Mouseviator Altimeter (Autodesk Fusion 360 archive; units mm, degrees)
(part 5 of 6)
sketch "Stepper Ear Pipe Outline" plane through (0, 39, 0) normal (0, 1, 0) x axis (-1, 0, 0)
  line L1 (-36.4994, -34.1766) -> (-41.1157, -22.3885)
  line L2 (-23.2139, -41.1177) -> (-33.6166, -37.0564)
  curve K1 (-21.3665, -41.4655) -> (-21.9088, -41.4365)
  line L3 (28.9018, -41.4655) -> (-21.3665, -41.4655)
  line L4 (41.4655, 20.5361) -> (41.4655, -28.9018)
  curve K2 (41.4365, 21.0784) -> (41.4655, 20.5361)
  line L5 (36.4994, 34.1766) -> (41.1157, 22.3885)
  line L6 (26.5185, 40.8706) -> (34.1546, 36.8093)
  line L7 (-24.1231, 41.4655) -> (24.1331, 41.4655)
  line L8 (-33.6166, 37.0564) -> (-26.5251, 40.8618)
  line L9 (-41.1157, 22.3885) -> (-36.4994, 34.1766)
  line L10 (12.6119, 7.2025) -> (15.0791, 9.6697)
  line L11 (20.0288, 4.7199) -> (17.5616, 2.2528)
  line L12 (-2.2528, -17.5616) -> (-4.7199, -20.0288)
  line L13 (-9.6697, -15.0791) -> (-7.2025, -12.6119)
  line L14 (-41.4655, -20.5361) -> (-41.4655, 20.5361)
  arc A1 centre (-36.3855, -20.5361) radius 5.08 clockwise from (-41.1157, -22.3885) to (-41.4655, -20.5361)
  arc A2 centre (-31.7692, -32.3242) radius 5.08 clockwise from (-33.6166, -37.0564) to (-36.4994, -34.1766)
  arc A3 centre (-21.3665, -36.3855) radius 5.08 clockwise from (-21.9088, -41.4365) to (-23.2139, -41.1177)
  arc A4 centre (28.9018, -28.9018) radius 12.5637 clockwise from (41.4655, -28.9018) to (28.9018, -41.4655)
  arc A5 centre (36.3855, 20.5361) radius 5.08 clockwise from (41.1157, 22.3885) to (41.4365, 21.0784)
  arc A6 centre (31.7692, 32.3242) radius 5.08 clockwise from (34.1546, 36.8093) to (36.4994, 34.1766)
  arc A7 centre (24.1331, 36.3855) radius 5.08 clockwise from (24.1331, 41.4655) to (26.5185, 40.8706)
  arc A8 centre (-24.1231, 36.3855) radius 5.08 clockwise from (-26.5251, 40.8618) to (-24.1231, 41.4655)
  arc A9 centre (-31.7692, 32.3242) radius 5.08 clockwise from (-36.4994, 34.1766) to (-33.6166, 37.0564)
  arc A10 centre (-36.3855, 20.5361) radius 5.08 clockwise from (-41.4655, 20.5361) to (-41.1157, 22.3885)
  circle C1 centre (-18.76, 36.96) radius 1
  circle C2 centre (31.4309, 31.4309) radius 2.159
  circle C3 centre (-31.4309, -31.4309) radius 2.159
  circle C4 centre (-18.76, -36.96) radius 1
  circle C5 centre (18.76, 36.96) radius 1
  circle C6 centre (-31.4309, 31.4309) radius 2.159
  circle C7 centre (0, 0) radius 5
  circle C8 centre (-36.96, 18.76) radius 1
  circle C9 centre (36.96, 18.76) radius 1
  circle C10 centre (-36.96, -18.76) radius 1
  arc A11 centre (5.1796, -5.1796) radius 14.4414 clockwise from (12.6119, 7.2025) to (17.5616, 2.2528)
  arc A12 centre (17.5539, 7.1948) radius 3.5 clockwise from (15.0791, 9.6697) to (20.0288, 4.7199)
  circle C11 centre (17.5539, 7.1948) radius 2
  arc A13 centre (5.1796, -5.1796) radius 14 clockwise from (-1.3868, -17.5442) to (-7.185, -11.7459)
  arc A14 centre (5.1796, -5.1796) radius 14 clockwise from (6.235, -19.1397) to (-1.3868, -17.5442)
  arc A15 centre (5.1796, -5.1796) radius 14 clockwise from (8.0318, -18.8859) to (6.235, -19.1397)
  closed curve K3 centre (5.1796, -5.1796)
  arc A16 centre (5.1796, -5.1796) radius 14 clockwise from (18.7748, -8.5217) to (8.5217, -18.7748)
  closed curve K4 centre (5.1796, -5.1796)
  arc A17 centre (5.1796, -5.1796) radius 14 clockwise from (19.1397, -6.235) to (18.8859, -8.0318)
  arc A18 centre (5.1796, -5.1796) radius 14 clockwise from (17.5442, 1.3868) to (19.1397, -6.235)
  arc A19 centre (5.1796, -5.1796) radius 14 clockwise from (11.7459, 7.185) to (17.5442, 1.3868)
  arc A20 centre (5.1796, -5.1796) radius 14 clockwise from (-0.4826, 7.6244) to (11.7459, 7.185)
  arc A21 centre (5.1796, -5.1796) radius 14 clockwise from (-7.6244, 0.4826) to (-0.4826, 7.6244)
  arc A22 centre (5.1796, -5.1796) radius 14 clockwise from (-7.185, -11.7459) to (-7.6244, 0.4826)
  circle C12 centre (5.1796, -5.1796) radius 14
  arc A23 centre (5.1796, -5.1796) radius 14.4414 clockwise from (-2.2528, -17.5616) to (-7.2025, -12.6119)
  arc A24 centre (-7.1948, -17.5539) radius 3.5 clockwise from (-4.7199, -20.0288) to (-9.6697, -15.0791)
  circle C13 centre (-7.1948, -17.5539) radius 2
sketch "Back Outline" plane through (0, 39, 0) normal (0, 1, 0) x axis (-1, 0, 0)
  line L1 (-36.4994, -34.1766) -> (-41.1157, -22.3885)
  line L2 (-23.2139, -41.1177) -> (-33.6166, -37.0564)
  curve K1 (-21.3665, -41.4655) -> (-21.9088, -41.4365)
  line L3 (28.9018, -41.4655) -> (-21.3665, -41.4655)
  line L4 (41.4655, 20.5361) -> (41.4655, -28.9018)
  curve K2 (41.4365, 21.0784) -> (41.4655, 20.5361)
  line L5 (36.4994, 34.1766) -> (41.1157, 22.3885)
  line L6 (26.5185, 40.8706) -> (34.1546, 36.8093)
  line L7 (-24.1231, 41.4655) -> (24.1331, 41.4655)
  line L8 (-33.6166, 37.0564) -> (-26.5251, 40.8618)
  line L9 (-41.1157, 22.3885) -> (-36.4994, 34.1766)
  line L10 (0, -31.4655) -> (0, 0)
  line L11 (-3.75, -18.1203) -> (-3.75, -31.4655)
  line L12 (3.75, -31.4655) -> (3.75, -0.2296)
  line L13 (0, 0) -> (30.9023, -30.9023)
  line L14 (-2.6517, -2.6517) -> (28.2507, -33.554)
  line L15 (2.6517, 2.6517) -> (33.554, -28.2507)
  line L16 (30.3606, 27.5008) -> (31.4655, 19.6071)
  line L17 (-20.4401, -31.4655) -> (-27.6044, -29.4666)
  line L18 (-22.8865, 31.4655) -> (-17.677, 31.4655)
  line L19 (-27.8686, 28.7921) -> (-22.8865, 31.4655)
  line L20 (-31.4655, 19.6071) -> (-27.8686, 28.7921)
  line L21 (-31.4655, 18.6813) -> (-31.4655, 19.6071)
  line L22 (30.4699, 22.1494) -> (31.4655, 19.6071)
  line L23 (-20.4401, -31.4655) -> (-25.1073, -29.6434)
  line L24 (28.9018, -31.4655) -> (-20.4401, -31.4655)
  line L25 (31.4655, 19.6071) -> (31.4655, -28.9018)
  line L26 (-41.4655, -20.5361) -> (-41.4655, 20.5361)
  arc A1 centre (-36.3855, -20.5361) radius 5.08 clockwise from (-41.1157, -22.3885) to (-41.4655, -20.5361)
  arc A2 centre (-31.7692, -32.3242) radius 5.08 clockwise from (-33.6166, -37.0564) to (-36.4994, -34.1766)
  arc A3 centre (-21.3665, -36.3855) radius 5.08 clockwise from (-21.9088, -41.4365) to (-23.2139, -41.1177)
  arc A4 centre (28.9018, -28.9018) radius 12.5637 clockwise from (41.4655, -28.9018) to (28.9018, -41.4655)
  arc A5 centre (36.3855, 20.5361) radius 5.08 clockwise from (41.1157, 22.3885) to (41.4365, 21.0784)
  arc A6 centre (31.7692, 32.3242) radius 5.08 clockwise from (34.1546, 36.8093) to (36.4994, 34.1766)
  arc A7 centre (24.1331, 36.3855) radius 5.08 clockwise from (24.1331, 41.4655) to (26.5185, 40.8706)
  arc A8 centre (-24.1231, 36.3855) radius 5.08 clockwise from (-26.5251, 40.8618) to (-24.1231, 41.4655)
  arc A9 centre (-31.7692, 32.3242) radius 5.08 clockwise from (-36.4994, 34.1766) to (-33.6166, 37.0564)
  arc A10 centre (-36.3855, 20.5361) radius 5.08 clockwise from (-41.4655, 20.5361) to (-41.1157, 22.3885)
  circle C1 centre (-18.76, 36.96) radius 1
  circle C2 centre (31.4309, 31.4309) radius 2.159
  circle C3 centre (-31.4309, -31.4309) radius 2.159
  circle C4 centre (-18.76, -36.96) radius 1
  circle C5 centre (18.76, 36.96) radius 1
  circle C6 centre (-31.4309, 31.4309) radius 2.159
  circle C7 centre (0, 0) radius 5
  circle C8 centre (-36.96, 18.76) radius 1
  circle C9 centre (36.96, 18.76) radius 1
  circle C10 centre (-36.96, -18.76) radius 1
  circle C11 centre (0, 0) radius 22.5
  circle C12 centre (30.9023, -30.9023) radius 15
  arc A11 centre (5.9161, 24.325) radius 24.65 clockwise from (-18.101, 18.7749) to (-17.677, 31.4655)
  arc A12 centre (-24.6171, -4.9983) radius 24.65 clockwise from (-31.4655, 18.6813) to (-18.101, 18.7749)
  arc A13 centre (5.9161, 24.325) radius 24.65 clockwise from (30.4699, 22.1494) to (-0.6001, 0.5519)
  arc A14 centre (-24.6171, -4.9983) radius 24.65 clockwise from (-0.6001, 0.5519) to (-25.1073, -29.6434)
  arc A15 centre (28.9018, -28.9018) radius 2.5637 clockwise from (31.4655, -28.9018) to (28.9018, -31.4655)
  point P1 (0, 0)
  point P59 (0, 0)
  point P60 (0, -31.4655)
  point P61 (-3.75, -31.4655)
  point P62 (-3.75, -18.1203)
  point P63 (3.75, -0.2296)
  point P64 (3.75, -31.4655)
  point P65 (0, 0)
  point P67 (0, 0)
  point P66 (30.9023, -30.9023)
  point P72 (30.9023, -30.9023)
  coincident P1 P59
  coincident P60 L24
  perpendicular L10 L24
  coincident P61 L24
  coincident P62 A14
  vertical L11
  coincident P63 A13
  coincident P64 L24
  perpendicular L12 L24
  coincident P1 P65
  coincident P1 P67
  coincident P66 P72
  concentric A4 A15
  tangent L24 A15
  tangent A15 L25
  dimension "d337_1" distance L10 L11 = 3.75 (= "( 7.5 / 2 ) * 1 mm")
  dimension "d338_1" distance L10 L12 = 3.75 (= "d337_1")
  dimension "d339_1" diameter C11 = 45
  dimension "d340_1" = -3.75 (= "( -7.5 / 2 ) * 1 mm")
  dimension "d341_1" = 3.75 (= "( 7.5 / 2 ) * 1 mm")
  dimension "d344_1" diameter C12 = 30
work_plane "WorkPlane2" AlongDistance 0.75 named "d269_1"
sketch "Sketch1" plane through (0, 8.25, 0) normal (0, 1, 0) x axis (1, 0, 0)
  line L1 (38.0143, -15.1613) -> (35.9057, -22.3587)
  line L2 (19.7873, -9.8212) -> (38.0143, -15.1613)
  line L3 (17.6786, -17.0187) -> (19.7873, -9.8212)
  line L4 (35.9057, -22.3587) -> (17.6786, -17.0187)
  line L5 (23.336, -34.9394) -> (14.184, -38.9806)
  line L6 (15.0207, -16.1078) -> (23.336, -34.9394)
  line L7 (5.8687, -20.149) -> (15.0207, -16.1078)
  line L8 (14.184, -38.9806) -> (5.8687, -20.149)
  line L9 (22.1039, 35.2627) -> (15.4161, 38.6573)
  line L10 (16.8157, 24.8442) -> (22.1039, 35.2627)
  line L11 (10.1279, 28.2387) -> (16.8157, 24.8442)
  line L12 (15.4161, 38.6573) -> (10.1279, 28.2387)
  line L13 (35.2627, 22.1039) -> (38.6573, 15.4161)
  line L14 (24.8442, 16.8157) -> (35.2627, 22.1039)
  line L15 (28.2387, 10.1279) -> (24.8442, 16.8157)
  line L16 (38.6573, 15.4161) -> (28.2387, 10.1279)
  line L17 (-35.8292, 20.0315) -> (-38.8758, 13.1782)
  line L18 (-25.675, 15.5175) -> (-35.8292, 20.0315)
  line L19 (-28.7216, 8.6642) -> (-25.675, 15.5175)
  line L20 (-38.8758, 13.1782) -> (-28.7216, 8.6642)
  line L21 (-13.9363, 38.5738) -> (-20.7275, 35.3911)
  line L22 (-9.2354, 28.5431) -> (-13.9363, 38.5738)
  line L23 (-16.0266, 25.3604) -> (-9.2354, 28.5431)
  line L24 (-20.7275, 35.3911) -> (-16.0266, 25.3604)
  circle C1 centre (0, 0) radius 30
  circle C2 centre (36.96, 18.76) radius 3.75
  circle C3 centre (36.96, -18.76) radius 3.75
  circle C4 centre (18.76, 36.96) radius 3.75
  circle C5 centre (-37.3525, 16.6048) radius 3.75
  circle C6 centre (-17.3319, 36.9825) radius 3.75
  circle C7 centre (18.76, -36.96) radius 3.75
  point P1 (0, 0)
  point P2 (0, 0)
  point P3 (35.9057, -22.3587)
  point P4 (38.0143, -15.1613)
  point P18 (36.96, -18.76)
  point P19 (18.76, -36.96)
  point P39 (18.76, -36.96)
  point P16 (36.96, -18.76)
  point P15 (36.96, 18.76)
  point P20 (36.96, 18.76)
  point P21 (18.76, 36.96)
  point P14 (10.1279, 28.2387)
  point P13 (16.8157, 24.8442)
  point P12 (22.1039, 35.2627)
  point P17 (18.76, 36.96)
  point P25 (28.2387, 10.1279)
  point P24 (24.8442, 16.8157)
  point P22 (38.6573, 15.4161)
  point P23 (35.2627, 22.1039)
  point P26 (36.96, 18.76)
  point P30 (-35.8292, 20.0315)
  point P29 (-38.8758, 13.1782)
  point P34 (-13.9363, 38.5738)
  point P33 (-20.7275, 35.3911)
  point P37 (-17.3319, 36.9825)
  point P28 (-17.3319, 36.9825)
  point P35 (-9.2354, 28.5431)
  point P36 (-16.0266, 25.3604)
  point P38 (-37.3525, 16.6048)
  point P32 (-28.7216, 8.6642)
  point P31 (-25.675, 15.5175)
  point P27 (-37.3525, 16.6048)
  coincident P1 P2
  perpendicular L1 L2
  parallel L1 L3
  parallel L2 L4
  perpendicular L5 L6
  parallel L5 L7
  parallel L6 L8
  perpendicular L9 L10
  parallel L9 L11
  parallel L10 L12
  coincident P3 C3
  coincident P4 C3
  midpoint L1 P18
  midpoint L5 P19
  coincident P19 P39
  coincident P16 P18
  coincident P15 P20
  midpoint L9 P21
  coincident C1 P14
  coincident C1 P13
  coincident P12 C4
  coincident P17 P21
  perpendicular L13 L14
  parallel L13 L15
  parallel L14 L16
  coincident C1 P25
  coincident C1 P24
  coincident C2 P22
  coincident C2 P23
  midpoint L13 P26
  perpendicular L17 L18
  parallel L17 L19
  parallel L18 L20
  coincident C5 P30
  coincident C5 P29
  perpendicular L21 L22
  parallel L21 L23
  parallel L22 L24
  coincident C6 P34
  coincident C6 P33
  midpoint L21 P37
  coincident P28 P37
  coincident C1 P35
  coincident C1 P36
  midpoint L17 P38
  coincident C1 P32
  coincident C1 P31
  coincident P27 P38
  dimension "d270_1" diameter C1 = 60
mirror "Mirror1" mirrorStitchTolerance 0.1 named "d277_1"
hole "Hole1" HoleDepth 6 named "d389_1" HoleDiameter 2.8 named "d390_1" TipAngle 180 named "d391_1"
delete_face "DeleteFace1"
work_plane "WorkPlane1" AlongDistance 0 named "d28_1_1"
work_plane "WorkPlane2" AlongDistance 30 named "d78_1_1"
extrude "Extrude1" new body blind 2.5 named "d29_2_1"
sketch "Motor Spacers" plane through (0, 39, 0) normal (0, 1, 0) x axis (-1, 0, 0)
  line L1 (36.4994, 34.1766) -> (41.1157, 22.3885)
  line L2 (26.5185, 40.8706) -> (34.1546, 36.8093)
  line L3 (-24.1231, 41.4655) -> (24.1331, 41.4655)
  line L4 (-33.6166, 37.0564) -> (-26.5251, 40.8618)
  line L5 (-41.1157, 22.3885) -> (-36.4994, 34.1766)
  line L6 (-41.4655, -20.5361) -> (-41.4655, 20.5361)
  line L7 (-36.4994, -34.1766) -> (-41.1157, -22.3885)
  line L8 (-23.2139, -41.1177) -> (-33.6166, -37.0564)
  curve K1 (-21.3665, -41.4655) -> (-21.9088, -41.4365)
  line L9 (28.9018, -41.4655) -> (-21.3665, -41.4655)
  line L10 (41.4655, 20.5361) -> (41.4655, -28.9018)
  curve K2 (41.4365, 21.0784) -> (41.4655, 20.5361)
  line L11 (-28.1171, -18.8029) -> (-28.1171, -22.4983)
  line L12 (-21.1171, -22.4983) -> (-21.1171, -18.8029)
  line L13 (-21.1171, 8.8064) -> (-21.1171, 12.5017)
  line L14 (-28.1171, 12.5017) -> (-28.1171, 8.8064)
  line L15 (-2.2528, -17.5616) -> (-4.7199, -20.0288)
  line L16 (-9.6697, -15.0791) -> (-7.2025, -12.6119)
  line L17 (12.6119, 7.2025) -> (15.0791, 9.6697)
  line L18 (20.0288, 4.7199) -> (17.5616, 2.2528)
  line L19 (19.7207, 20.825) -> (23.4161, 20.825)
  line L20 (23.4161, 27.825) -> (19.7207, 27.825)
  line L21 (-7.8886, 27.825) -> (-11.5839, 27.825)
  line L22 (-11.5839, 20.825) -> (-7.8886, 20.825)
  circle C1 centre (36.96, 18.76) radius 1
  circle C2 centre (18.76, 36.96) radius 1
  circle C3 centre (-36.96, -18.76) radius 1
  circle C4 centre (-31.4309, -31.4309) radius 2.159
  circle C5 centre (31.4309, 31.4309) radius 2.159
  arc A1 centre (36.3855, 20.5361) radius 5.08 clockwise from (41.1157, 22.3885) to (41.4365, 21.0784)
  arc A2 centre (31.7692, 32.3242) radius 5.08 clockwise from (34.1546, 36.8093) to (36.4994, 34.1766)
  arc A3 centre (24.1331, 36.3855) radius 5.08 clockwise from (24.1331, 41.4655) to (26.5185, 40.8706)
  arc A4 centre (-24.1231, 36.3855) radius 5.08 clockwise from (-26.5251, 40.8618) to (-24.1231, 41.4655)
  arc A5 centre (-31.7692, 32.3242) radius 5.08 clockwise from (-36.4994, 34.1766) to (-33.6166, 37.0564)
  arc A6 centre (-36.3855, 20.5361) radius 5.08 clockwise from (-41.4655, 20.5361) to (-41.1157, 22.3885)
  arc A7 centre (-36.3855, -20.5361) radius 5.08 clockwise from (-41.1157, -22.3885) to (-41.4655, -20.5361)
  arc A8 centre (-31.7692, -32.3242) radius 5.08 clockwise from (-33.6166, -37.0564) to (-36.4994, -34.1766)
  arc A9 centre (-21.3665, -36.3855) radius 5.08 clockwise from (-21.9088, -41.4365) to (-23.2139, -41.1177)
  arc A10 centre (28.9018, -28.9018) radius 12.5637 clockwise from (41.4655, -28.9018) to (28.9018, -41.4655)
  arc A11 centre (-24.6171, -4.9983) radius 14.2414 clockwise from (-21.1171, -18.8029) to (-28.1171, -18.8029)
  arc A12 centre (-24.6171, -22.4983) radius 3.5 clockwise from (-21.1171, -22.4983) to (-28.1171, -22.4983)
  circle C6 centre (-24.6171, -22.4983) radius 2
  arc A13 centre (-24.6171, -4.9983) radius 14.2414 clockwise from (-28.1171, 8.8064) to (-21.1171, 8.8064)
  arc A14 centre (-24.6171, 12.5017) radius 3.5 clockwise from (-28.1171, 12.5017) to (-21.1171, 12.5017)
  circle C7 centre (-24.6171, 12.5017) radius 2
  arc A15 centre (5.1796, -5.1796) radius 14.4414 clockwise from (-2.2528, -17.5616) to (-7.2025, -12.6119)
  arc A16 centre (-7.1948, -17.5539) radius 3.5 clockwise from (-4.7199, -20.0288) to (-9.6697, -15.0791)
  circle C8 centre (-7.1948, -17.5539) radius 2
  arc A17 centre (5.1796, -5.1796) radius 14.4414 clockwise from (12.6119, 7.2025) to (17.5616, 2.2528)
  arc A18 centre (17.5539, 7.1948) radius 3.5 clockwise from (15.0791, 9.6697) to (20.0288, 4.7199)
  circle C9 centre (17.5539, 7.1948) radius 2
  arc A19 centre (5.9161, 24.325) radius 14.2414 clockwise from (19.7207, 27.825) to (19.7207, 20.825)
  arc A20 centre (23.4161, 24.325) radius 3.5 clockwise from (23.4161, 27.825) to (23.4161, 20.825)
  circle C10 centre (23.4161, 24.325) radius 2
  arc A21 centre (5.9161, 24.325) radius 14.2414 clockwise from (-7.8886, 20.825) to (-7.8886, 27.825)
  arc A22 centre (-11.5839, 24.325) radius 3.5 clockwise from (-11.5839, 20.825) to (-11.5839, 27.825)
  circle C11 centre (-11.5839, 24.325) radius 2
  circle C12 centre (-24.6171, -22.4983) radius 1.4
  circle C13 centre (-24.6171, 12.5017) radius 1.4
  circle C14 centre (-7.1948, -17.5539) radius 1.4
  circle C15 centre (17.5539, 7.1948) radius 1.4
  circle C16 centre (23.4161, 24.325) radius 1.4
  circle C17 centre (-11.5839, 24.325) radius 1.4
  circle C18 centre (-18.76, -36.96) radius 1
  circle C19 centre (0, 0) radius 5
  circle C20 centre (-31.4309, 31.4309) radius 2.159
  circle C21 centre (-36.96, 18.76) radius 1
  circle C22 centre (-18.76, 36.96) radius 1
  circle C23 centre (30.9023, -30.9023) radius 5.5
  point P68 (23.4161, 24.325)
  point P79 (23.4161, 24.325)
  concentric A12 C12
  concentric A14 C13
  concentric A16 C14
  concentric A18 C15
  coincident P68 P79
  concentric A22 C17
  equal C16 C17
  equal C15 C16
  equal C14 C15
  equal C12 C14
  equal C12 C13
  dimension "d76_1_1" diameter C13 = 2.8
sketch "Standoffs" plane through (0, 36.5, 0) normal (0, -1, 0) x axis (1, 0, 0)
  curve K1 (-41.4655, 20.5361) -> (-41.4365, 21.0784)
  line L1 (-41.4655, -28.9018) -> (-41.4655, 20.5361)
  line L2 (21.3665, -41.4655) -> (-28.9018, -41.4655)
  curve K2 (21.9088, -41.4365) -> (21.3665, -41.4655)
  line L3 (33.6166, -37.0564) -> (23.2139, -41.1177)
  line L4 (41.1157, -22.3885) -> (36.4994, -34.1766)
  line L5 (41.4655, 20.5361) -> (41.4655, -20.5361)
  line L6 (36.4994, 34.1766) -> (41.1157, 22.3885)
  line L7 (26.5251, 40.8618) -> (33.6166, 37.0564)
  line L8 (-24.1331, 41.4655) -> (24.1231, 41.4655)
  line L9 (-34.1546, 36.8093) -> (-26.5185, 40.8706)
  line L10 (-41.1157, 22.3885) -> (-36.4994, 34.1766)
  arc A1 centre (-36.3855, 20.5361) radius 5.08 clockwise from (-41.4365, 21.0784) to (-41.1157, 22.3885)
  arc A2 centre (-28.9018, -28.9018) radius 12.5637 clockwise from (-28.9018, -41.4655) to (-41.4655, -28.9018)
  arc A3 centre (21.3665, -36.3855) radius 5.08 clockwise from (23.2139, -41.1177) to (21.9088, -41.4365)
  arc A4 centre (31.7692, -32.3242) radius 5.08 clockwise from (36.4994, -34.1766) to (33.6166, -37.0564)
  arc A5 centre (36.3855, -20.5361) radius 5.08 clockwise from (41.4655, -20.5361) to (41.1157, -22.3885)
  arc A6 centre (36.3855, 20.5361) radius 5.08 clockwise from (41.1157, 22.3885) to (41.4655, 20.5361)
  arc A7 centre (31.7692, 32.3242) radius 5.08 clockwise from (33.6166, 37.0564) to (36.4994, 34.1766)
  arc A8 centre (24.1231, 36.3855) radius 5.08 clockwise from (24.1231, 41.4655) to (26.5251, 40.8618)
  arc A9 centre (-24.1331, 36.3855) radius 5.08 clockwise from (-26.5185, 40.8706) to (-24.1331, 41.4655)
  arc A10 centre (-31.7692, 32.3242) radius 5.08 clockwise from (-36.4994, 34.1766) to (-34.1546, 36.8093)
  circle C1 centre (18.76, -36.96) radius 1
  circle C2 centre (-31.4309, 31.4309) radius 2.159
  circle C3 centre (18.76, 36.96) radius 1
  circle C4 centre (-18.76, 36.96) radius 1
  circle C5 centre (31.4309, -31.4309) radius 2.159
  circle C6 centre (31.4309, 31.4309) radius 2.159
  circle C7 centre (-18.76, 36.96) radius 4.0817
  circle C8 centre (18.76, 36.96) radius 3.75
  circle C9 centre (36.96, 18.76) radius 3.75
  circle C10 centre (36.96, -18.76) radius 3.75
  circle C11 centre (18.76, -36.96) radius 3.75
  circle C12 centre (-37.3525, -16.6048) radius 3.75
  circle C13 centre (-17.3319, -36.9825) radius 3.75
  circle C14 centre (-37.3525, -16.6048) radius 1
  circle C15 centre (-17.3319, -36.9825) radius 1
  circle C16 centre (-36.96, 18.76) radius 1
  circle C17 centre (0, 0) radius 5
  circle C18 centre (36.96, -18.76) radius 1
  circle C19 centre (36.96, 18.76) radius 1
  circle C20 centre (-36.96, 18.76) radius 3.75
  point P42 (36.96, -18.76)
  point P53 (36.96, -18.76)
  point P41 (36.96, 18.76)
  point P54 (36.96, 18.76)
  point P1 (0, 0)
  point P44 (-37.3525, -16.6048)
  point P45 (-17.3319, -36.9825)
  concentric C4 C7
  concentric C3 C8
  concentric C1 C11
  equal C8 C9
  equal C9 C10
  equal C10 C11
  concentric C12 C14
  concentric C13 C15
  equal C14 C15
  equal C1 C14
  equal C11 C12
  coincident P42 P53
  coincident P41 P54
  concentric C16 C20
  equal C13 C20
  dimension "d182_1_1" diameter C8 = 7.5
  dimension "d282_1_1" distance P1 P44 = 16.6048 (= "18.6048175707 mm - 2 mm")
  dimension "d283_1_1" distance P1 P44 = 37.3525
  dimension "d284_1_1" distance P1 P45 = 17.3319 (= "19.3319078447 mm - 2 mm")
  dimension "d285_1_1" distance P1 P45 = 36.9825
sketch "Back Outline" plane through (0, 39, 0) normal (0, 1, 0) x axis (-1, 0, 0)
  line L1 (-36.4994, -34.1766) -> (-41.1157, -22.3885)
  line L2 (-23.2139, -41.1177) -> (-33.6166, -37.0564)
  curve K1 (-21.3665, -41.4655) -> (-21.9088, -41.4365)
  line L3 (28.9018, -41.4655) -> (-21.3665, -41.4655)
  line L4 (41.4655, 20.5361) -> (41.4655, -28.9018)
  curve K2 (41.4365, 21.0784) -> (41.4655, 20.5361)
  line L5 (36.4994, 34.1766) -> (41.1157, 22.3885)
  line L6 (26.5185, 40.8706) -> (34.1546, 36.8093)
  line L7 (-24.1231, 41.4655) -> (24.1331, 41.4655)
  line L8 (-33.6166, 37.0564) -> (-26.5251, 40.8618)
  line L9 (-41.1157, 22.3885) -> (-36.4994, 34.1766)
  line L10 (0, -31.4655) -> (0, 0)
  line L11 (-3.75, -18.1203) -> (-3.75, -31.4655)
  line L12 (3.75, -31.4655) -> (3.75, -0.2296)
  line L13 (0, 0) -> (30.9023, -30.9023)
  line L14 (-2.6517, -2.6517) -> (28.2507, -33.554)
  line L15 (2.6517, 2.6517) -> (33.554, -28.2507)
  line L16 (30.3606, 27.5008) -> (31.4655, 19.6071)
  line L17 (-20.4401, -31.4655) -> (-27.6044, -29.4666)
  line L18 (-22.8865, 31.4655) -> (-17.677, 31.4655)
  line L19 (-27.8686, 28.7921) -> (-22.8865, 31.4655)
  line L20 (-31.4655, 19.6071) -> (-27.8686, 28.7921)
  line L21 (-31.4655, 18.6813) -> (-31.4655, 19.6071)
  line L22 (30.4699, 22.1494) -> (31.4655, 19.6071)
  line L23 (-20.4401, -31.4655) -> (-25.1073, -29.6434)
  line L24 (28.9018, -31.4655) -> (-20.4401, -31.4655)
  line L25 (31.4655, 19.6071) -> (31.4655, -28.9018)
  line L26 (-41.4655, -20.5361) -> (-41.4655, 20.5361)
  arc A1 centre (-36.3855, -20.5361) radius 5.08 clockwise from (-41.1157, -22.3885) to (-41.4655, -20.5361)
  arc A2 centre (-31.7692, -32.3242) radius 5.08 clockwise from (-33.6166, -37.0564) to (-36.4994, -34.1766)
  arc A3 centre (-21.3665, -36.3855) radius 5.08 clockwise from (-21.9088, -41.4365) to (-23.2139, -41.1177)
  arc A4 centre (28.9018, -28.9018) radius 12.5637 clockwise from (41.4655, -28.9018) to (28.9018, -41.4655)
  arc A5 centre (36.3855, 20.5361) radius 5.08 clockwise from (41.1157, 22.3885) to (41.4365, 21.0784)
  arc A6 centre (31.7692, 32.3242) radius 5.08 clockwise from (34.1546, 36.8093) to (36.4994, 34.1766)
  arc A7 centre (24.1331, 36.3855) radius 5.08 clockwise from (24.1331, 41.4655) to (26.5185, 40.8706)
  arc A8 centre (-24.1231, 36.3855) radius 5.08 clockwise from (-26.5251, 40.8618) to (-24.1231, 41.4655)
  arc A9 centre (-31.7692, 32.3242) radius 5.08 clockwise from (-36.4994, 34.1766) to (-33.6166, 37.0564)
  arc A10 centre (-36.3855, 20.5361) radius 5.08 clockwise from (-41.4655, 20.5361) to (-41.1157, 22.3885)
  circle C1 centre (-18.76, 36.96) radius 1
  circle C2 centre (31.4309, 31.4309) radius 2.159
  circle C3 centre (-31.4309, -31.4309) radius 2.159
  circle C4 centre (-18.76, -36.96) radius 1
  circle C5 centre (18.76, 36.96) radius 1
  circle C6 centre (-31.4309, 31.4309) radius 2.159
  circle C7 centre (-36.96, 18.76) radius 1
  circle C8 centre (36.96, 18.76) radius 1
  circle C9 centre (-36.96, -18.76) radius 1
  circle C10 centre (0, 0) radius 22.5
  circle C11 centre (30.9023, -30.9023) radius 15
  arc A11 centre (5.9161, 24.325) radius 24.65 clockwise from (-18.101, 18.7749) to (-17.677, 31.4655)
  arc A12 centre (-24.6171, -4.9983) radius 24.65 clockwise from (-31.4655, 18.6813) to (-18.101, 18.7749)
  arc A13 centre (5.9161, 24.325) radius 24.65 clockwise from (30.4699, 22.1494) to (-0.6001, 0.5519)
  arc A14 centre (-24.6171, -4.9983) radius 24.65 clockwise from (-0.6001, 0.5519) to (-25.1073, -29.6434)
  arc A15 centre (28.9018, -28.9018) radius 2.5637 clockwise from (31.4655, -28.9018) to (28.9018, -31.4655)
  circle C12 centre (36.96, 18.76) radius 1
  circle C13 centre (37.04, -14.76) radius 1
  point P1 (0, 0)
  point P58 (0, 0)
  point P59 (0, -31.4655)
  point P60 (-3.75, -31.4655)
  point P61 (-3.75, -18.1203)
  point P62 (3.75, -0.2296)
  point P63 (3.75, -31.4655)
  point P64 (0, 0)
  point P66 (0, 0)
  point P65 (30.9023, -30.9023)
  point P71 (30.9023, -30.9023)
  coincident P1 P58
  coincident P59 L24
  perpendicular L10 L24
  coincident P60 L24
  coincident P61 A14
  vertical L11
  coincident P62 A13
  coincident P63 L24
  perpendicular L12 L24
  coincident P1 P64
  coincident P1 P66
  coincident P65 P71
  concentric A4 A15
  tangent L24 A15
  tangent A15 L25
  dimension "d337_1_1" distance L10 L11 = 3.75 (= "( 7.5 / 2 ) * 1 mm")
  dimension "d338_1_1" distance L10 L12 = 3.75 (= "d337_1_1")
  dimension "d339_1_1" diameter C10 = 45
  dimension "d340_1_1" = -3.75 (= "( -7.5 / 2 ) * 1 mm")
  dimension "d341_1_1" = 3.75 (= "( 7.5 / 2 ) * 1 mm")
  dimension "d344_1_1" diameter C11 = 30
work_plane "WorkPlane2" AlongDistance 0.75 named "d269_1_1"
mirror "Mirror1" mirrorStitchTolerance 0.1 named "d277_1_1"
hole "Hole1" HoleDepth 6 named "d389_1_1" HoleDiameter 2.8 named "d390_1_1" TipAngle 180 named "d391_1_1"
delete_face "DeleteFace1"
component_insert "Component Insert1"
component_insert "Component Insert2"
component_insert "Component Insert3"
delete_face "DeleteFace2"
delete_face "DeleteFace3"
delete_face "DeleteFace4"
position "Position5"
sketch "Board outlines" plane through (0, 39, 0) normal (0, 1, 0) x axis (1, 0, 0)
  line L1 (34.2136, -34.0172) -> (34.2136, -0.5172)
  line L2 (3.2136, -34.0172) -> (34.2136, -34.0172)
  line L3 (3.2136, -0.5172) -> (3.2136, -34.0172)
  line L4 (34.2136, -0.5172) -> (3.2136, -0.5172)
  line L5 (34.2136, -0.5172) -> (3.2136, -34.0172)
  line L6 (3.2136, -0.5172) -> (34.2136, -34.0172)
  line L7 (-1.0895, -33.9863) -> (-1.0895, -0.4863)
  line L8 (-32.0895, -33.9863) -> (-1.0895, -33.9863)
  line L9 (-32.0895, -0.4863) -> (-32.0895, -33.9863)
  line L10 (-1.0895, -0.4863) -> (-32.0895, -0.4863)
  line L11 (-1.0895, -0.4863) -> (-32.0895, -33.9863)
  line L12 (-32.0895, -0.4863) -> (-1.0895, -33.9863)
  line L13 (-32.3717, 4.3797) -> (1.1283, 4.3797)
  line L14 (-32.3717, 35.3797) -> (-32.3717, 4.3797)
  line L15 (1.1283, 35.3797) -> (-32.3717, 35.3797)
  line L16 (1.1283, 4.3797) -> (1.1283, 35.3797)
  line L17 (-36.4994, -34.1766) -> (-41.1157, -22.3885)
  line L18 (-26.5185, -40.8706) -> (-34.1546, -36.8093)
  line L19 (24.1231, -41.4655) -> (-24.1331, -41.4655)
  line L20 (33.6166, -37.0564) -> (26.5251, -40.8618)
  line L21 (41.1157, -22.3885) -> (36.4994, -34.1766)
  line L22 (41.4655, 20.5361) -> (41.4655, -20.5361)
  line L23 (36.4994, 34.1766) -> (41.1157, 22.3885)
  line L24 (23.2139, 41.1177) -> (33.6166, 37.0564)
  curve K1 (21.3665, 41.4655) -> (21.9088, 41.4365)
  line L25 (-28.9018, 41.4655) -> (21.3665, 41.4655)
  line L26 (-41.4655, -20.5361) -> (-41.4655, 28.9018)
  curve K2 (-41.4365, -21.0784) -> (-41.4655, -20.5361)
  line L27 (-40, -14) -> (-35, -14)
  line L28 (-40, 12) -> (-40, -14)
  line L29 (-35, 12) -> (-40, 12)
  line L30 (-35, -14) -> (-35, 12)
  line L31 (34.1616, 34.6741) -> (38.4785, 23.6504)
  line L32 (23.7487, 38.7393) -> (34.1616, 34.6741)
  line L33 (21.8646, 33.9133) -> (23.7487, 38.7393)
  line L34 (30.1616, 30.6741) -> (21.8646, 33.9133)
  line L35 (33.6522, 21.7604) -> (30.1616, 30.6741)
  line L36 (38.4785, 23.6504) -> (33.6522, 21.7604)
  circle C1 centre (5.2136, -2.5172) radius 1.375
  circle C2 centre (32.2136, -2.5172) radius 1.375
  circle C3 centre (32.2136, -32.0172) radius 1.375
  circle C4 centre (5.2136, -32.0172) radius 1.375
  circle C5 centre (-30.0895, -2.4863) radius 1.375
  circle C6 centre (-3.0895, -2.4863) radius 1.375
  circle C7 centre (-3.0895, -31.9863) radius 1.375
  circle C8 centre (-30.0895, -31.9863) radius 1.375
  circle C9 centre (-30.3717, 6.3797) radius 1.375
  circle C10 centre (-0.8717, 6.3797) radius 1.375
  circle C11 centre (-30.3717, 33.3797) radius 1.375
  circle C12 centre (-0.8717, 33.3797) radius 1.375
  circle C13 centre (15, 14) radius 10
  circle C14 centre (18.76, 36.96) radius 1.4
  circle C15 centre (-37.3525, 16.6048) radius 1.4
  circle C16 centre (-18.76, -36.96) radius 1.4
  circle C17 centre (36.96, -18.76) radius 1.4
  circle C18 centre (18.76, -36.96) radius 1.4
  circle C19 centre (-36.96, -18.76) radius 1.4
  circle C20 centre (-17.3319, 36.9825) radius 1.4
  circle C21 centre (36.96, 18.76) radius 1.4
  arc A1 centre (-36.3855, -20.5361) radius 5.08 clockwise from (-41.1157, -22.3885) to (-41.4365, -21.0784)
  arc A2 centre (-31.7692, -32.3242) radius 5.08 clockwise from (-34.1546, -36.8093) to (-36.4994, -34.1766)
  arc A3 centre (-24.1331, -36.3855) radius 5.08 clockwise from (-24.1331, -41.4655) to (-26.5185, -40.8706)
  arc A4 centre (24.1231, -36.3855) radius 5.08 clockwise from (26.5251, -40.8618) to (24.1231, -41.4655)
  arc A5 centre (31.7692, -32.3242) radius 5.08 clockwise from (36.4994, -34.1766) to (33.6166, -37.0564)
  arc A6 centre (36.3855, -20.5361) radius 5.08 clockwise from (41.4655, -20.5361) to (41.1157, -22.3885)
  arc A7 centre (36.3855, 20.5361) radius 5.08 clockwise from (41.1157, 22.3885) to (41.4655, 20.5361)
  arc A8 centre (31.7692, 32.3242) radius 5.08 clockwise from (33.6166, 37.0564) to (36.4994, 34.1766)
  arc A9 centre (21.3665, 36.3855) radius 5.08 clockwise from (21.9088, 41.4365) to (23.2139, 41.1177)
  arc A10 centre (-28.9018, 28.9018) radius 12.5637 clockwise from (-41.4655, 28.9018) to (-28.9018, 41.4655)
  point P3 (34.2136, -0.5172)
  point P4 (3.2136, -0.5172)
  point P6 (3.2136, -34.0172)
  point P9 (5.2136, -2.5172)
  point P11 (-1.0895, -0.4863)
  point P12 (-32.0895, -0.4863)
  point P14 (-32.0895, -33.9863)
  point P17 (-30.0895, -2.4863)
  point P18 (1.1283, 4.3797)
  point P19 (-32.3717, 4.3797)
  point P22 (-30.3717, 6.3797)
  point P34 (36.96, 18.76)
  point P27 (18.76, 36.96)
  point P23 (-0.8717, 6.3797)
  point P25 (-0.8717, 33.3797)
  point P24 (-30.3717, 33.3797)
  point P15 (-3.0895, -2.4863)
  point P10 (-30.0895, -31.9863)
  point P16 (-3.0895, -31.9863)
  point P2 (5.2136, -32.0172)
  point P8 (32.2136, -32.0172)
  point P7 (32.2136, -2.5172)
  perpendicular L2 L3
  parallel L2 L4
  parallel L1 L3
  horizontal L2
  perpendicular L8 L9
  parallel L8 L10
  parallel L7 L9
  horizontal L8
  horizontal L13
  vertical L14
  horizontal L15
  vertical L16
  horizontal L27
  vertical L28
  horizontal L29
  vertical L30
  parallel L23 L31
  parallel L24 L32
  perpendicular L32 L33
  perpendicular L33 L34
  parallel L31 L35
  perpendicular L35 L36
  dimension "d433" distance P3 P4 = 31
  dimension "d434" distance P4 P6 = 33.5
  dimension "d435" diameter C1 = 2.75
  dimension "d436" distance P9 L3 = 2
  dimension "d437" distance P9 L4 = 2
  dimension "d442" distance P11 P12 = 31
  dimension "d443" distance P12 P14 = 33.5
  dimension "d444" diameter C5 = 2.75
  dimension "d445" distance P17 L9 = 2
  dimension "d446" distance P17 L10 = 2
  dimension "d456" distance P18 P19 = 33.5
  dimension "d457" distance L13 L15 = 31
  dimension "d458" diameter C9 = 2.75
  dimension "d459" distance L14 P22 = 2
  dimension "d460" distance L13 P22 = 2
  dimension "d470" diameter C13 = 20
  dimension "d478" distance P34 L36 = 4
  dimension "d479" distance P27 L33 = 4
  dimension "d493" distance L13 P23 = 2
  dimension "d494" distance L16 P23 = 2
  dimension "d495" distance L16 P25 = 2
  dimension "d496" distance L14 P24 = 2
  dimension "d497" distance L15 P24 = 2
  dimension "d498" distance L15 P25 = 2
  dimension "d499" distance P15 L7 = 2
  dimension "d500" distance P10 L9 = 2
  dimension "d501" distance P10 L8 = 2
  dimension "d502" distance P16 L8 = 2
  dimension "d503" distance P16 L7 = 2
  dimension "d504" distance P2 L3 = 2
  dimension "d505" distance P2 L2 = 2
  dimension "d506" distance P8 L2 = 2
  dimension "d507" distance P8 L1 = 2
  dimension "d508" distance P7 L1 = 2
  dimension "d509" distance P7 L4 = 2
  dimension "d510" distance P15 L10 = 2
extrude "Extrude16" add sketch "Board outlines" profile of C1 C2 C3 C4 C5 C6 C7 C8 C9 C10 C11 C12 along normal blind 7 Side1WallThickness 1.5
extrude "Extrude17" cut sketch "Board outlines" profile of C13 no distance stored
fillet "Fillet4" radius 1
extrude "Extrude18" add sketch "Board outlines" profile of L31 L32 L33 L34 L35 L36 along normal blind 10
extrude "Extrude19" add sketch "Board outlines" profile of L27 L28 L29 L30 along normal blind 10
position "Position6"
sketch "VCC cutouts" plane through (-40, 0, 0) normal (-1, 0, 0) x axis (0, -1, 0)
  line L1 (-39, 14) -> (-39, -12)
  line L2 (-49, 14) -> (-39, 14)
  line L3 (-49, -12) -> (-49, 14)
  line L4 (-39, -12) -> (-49, -12)
  circle C1 centre (-44, 9) radius 3
  circle C2 centre (-44, -7) radius 3
  circle C3 centre (-44, 1) radius 3
  dimension "d484" diameter C1 = 6
  dimension "d485" diameter C2 = 6
  dimension "d486" diameter C3 = 6
extrude "Extrude20" cut sketch "VCC cutouts" profile of C1 C2 C3 against normal blind 6
sketch "Cable cutout 1" plane through (36.5661, 0, -14.3196) normal (-0.9311, 0, 0.3646) x axis (0, -1, 0)
  line L1 (-39, -7.991) -> (-39, -17.5638)
  line L2 (-49, -7.991) -> (-39, -7.991)
  line L3 (-49, -17.5638) -> (-49, -7.991)
  line L4 (-39, -17.5638) -> (-49, -17.5638)
  circle C1 centre (-44, -12.7774) radius 3.5
  dimension "d489" diameter C1 = 7
sketch "Cable cutout 2" plane through (14.3806, 0, -36.835) normal (-0.3637, 0, 0.9315) x axis (0, -1, 0)
  line L1 (-39, 16.941) -> (-39, 8.0341)
  line L2 (-49, 16.941) -> (-39, 16.941)
  line L3 (-49, 8.0341) -> (-49, 16.941)
  line L4 (-39, 8.0341) -> (-49, 8.0341)
  circle C1 centre (-44, 12.4876) radius 3.5
  dimension "d490" diameter C1 = 7
extrude "Extrude21" cut sketch "Cable cutout 1" profile of C1 no distance stored
extrude "Extrude22" cut sketch "Cable cutout 2" profile of C1 no distance stored
position "Position4"
position "Position4"
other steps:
derived_base_feature "Derived Base Feature1"
derived_base_feature "Derived Base Feature1" bodies "Body1", "Body2"
derived_base_feature "Top Sketch" bodies "Body1", "Top LED Holder"
derived_base_feature "Derived Base Feature1" bodies "Body1", "Body2"
derived_base_feature "Sketch1" bodies "Body1"
derived_base_feature "Sketch1" bodies "Body2", "Seal"
base_feature "Base Feature1" bodies "10K Needle Gear"
base_feature "Base Feature1" bodies "10K Needle"
base_feature "Base Feature1" bodies "10K Needle 2nd Version"
derived_base_feature "Front Face" bodies "ALT VSI Bezel"
hole "Hole1" HoleDepth 4 HoleDiameter 5 TipAngle 180
hole "Hole1" HoleDepth 19.75 HoleDiameter 6.5 TipAngle 180
fillet "Fillet1" radius 0.5
fillet "Fillet1" radius 0.5
chamfer "Chamfer1" distance 0.5
base_feature "Base Feature1" bodies "10K Needle", "10K Needle 2nd Version"
hole "Hole2" HoleDepth 19.75 HoleDiameter 6.5 TipAngle 180
hole "Hole3" HoleDepth 19 HoleDiameter 2.8 TipAngle 180
create_component "CreateComponent1"
create_component "CreateComponent2"
create_component "CreateComponent3"
create_component "CreateComponent4"
create_component "CreateComponent5"
create_component "CreateComponent6"
create_component "CreateComponent7"
create_component "CreateComponent8"
create_component "CreateComponent9"
create_component "CreateComponent10"
create_component "CreateComponent11"
create_component "CreateComponent12"
remove_instance "RemoveInstance1"
create_component "CreateComponent13"
create_component "CreateComponent1"
create_component "CreateComponent2"
create_component "CreateComponent3"
create_component "CreateComponent14"
remove_instance "RemoveInstance1"
remove_instance "RemoveInstance2"
remove_instance "RemoveInstance3"
joint_origin "JointOrigin26"
create_component "CreateComponent15"
create_component "CreateComponent16"
create_component "CreateComponent1"
create_component "CreateComponent2"
joint_origin "JointOrigin36"
create_component "CreateComponent17"
joint_origin "JointOrigin41"
joint_origin "JointOrigin43"
joint_origin "JointOrigin44"
create_component "CreateComponent1"
remove_body "RemoveBody1"
create_component "CreateComponent2"
remove_body "RemoveBody2"
create_component "CreateComponent3"
remove_body "RemoveBody3"
create_component "CreateComponent18"
create_component "CreateComponent2"
create_component "CreateComponent2"
create_component "CreateComponent19"
create_component "CreateComponent20"
named bodies: "ALT VSI Bezel", "Body2", "Body1", "Seal", "Top LED Holder", "Faceplate", "Wheel", "10K Needle", "1K Needle", "100ft Needle", "1K Needle Gear", "10K Needle Gear", "10K Needle 2nd Version"

design "10 turn potentiometer"
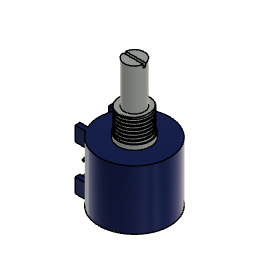
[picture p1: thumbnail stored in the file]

design "Bezel LED and Glass MS33638C" references "LED D5 - White-Clear"
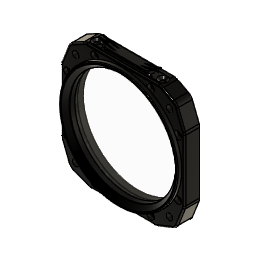
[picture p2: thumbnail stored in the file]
parameter "d52" = 0.15
canvas "Canvas4"
canvas "Canvas1"
sketch "Instrument Sketch" plane through (0, 0, 0) normal (1, 0, 0) x axis (0, 1, 0)
  line L1 (-41.4655, 20.5361) -> (-41.4655, 0)
  line L2 (-36.4994, 34.1766) -> (-41.1157, 22.3885)
  line L3 (-23.2139, 41.1177) -> (-33.6166, 37.0564)
  line L4 (0, 41.4655) -> (-21.3665, 41.4655)
  line L5 (0, 22.5) -> (0, 0)
  line L6 (0, 0) -> (0, 41.4655)
  line L7 (-41.4655, 0) -> (0, 0)
  line L8 (41.4655, 20.5361) -> (41.4655, 0)
  line L9 (36.4994, 34.1766) -> (41.1157, 22.3885)
  line L10 (23.2139, 41.1177) -> (33.6166, 37.0564)
  line L11 (0, 41.4655) -> (21.3665, 41.4655)
  line L12 (-41.4655, -20.5361) -> (-41.4655, 0)
  line L13 (-36.4994, -34.1766) -> (-41.1157, -22.3885)
  line L14 (-23.2139, -41.1177) -> (-33.6166, -37.0564)
  line L15 (0, -41.4655) -> (-21.3665, -41.4655)
  line L16 (41.4655, -20.5361) -> (41.4655, 0)
  line L17 (36.4994, -34.1766) -> (41.1157, -22.3885)
  line L18 (0, -41.4655) -> (21.3665, -41.4655)
  line L19 (23.2139, -41.1177) -> (33.6166, -37.0564)
  line L20 (-1.0967, 0) -> (0, 0)
  line L21 (-72.2485, 72.2485) -> (0, 0)
  line L22 (24.1231, 41.4655) -> (-24.1331, 41.4655)
  line L23 (26.5251, 40.8618) -> (33.6166, 37.0564)
  line L24 (-34.1546, 36.8093) -> (-26.5185, 40.8706)
  circle C1 centre (0, 0) radius 39.6875
  circle C2 centre (31.4309, 31.4309) radius 2.159
  circle C3 centre (-31.4309, -31.4309) radius 2.159
  circle C4 centre (-31.4309, 31.4309) radius 2.159
  circle C5 centre (31.4309, -31.4309) radius 2.159
  arc A1 centre (-31.7692, 32.3242) radius 5.08 clockwise from (-36.4994, 34.1766) to (-33.6166, 37.0564)
  arc A2 centre (-21.3665, 36.3855) radius 5.08 clockwise from (-23.2139, 41.1177) to (-21.3665, 41.4655)
  arc A3 centre (-36.3855, 20.5361) radius 5.08 clockwise from (-41.4655, 20.5361) to (-41.1157, 22.3885)
  arc A4 centre (36.3855, 20.5361) radius 5.08 clockwise from (41.1157, 22.3885) to (41.4655, 20.5361)
  arc A5 centre (31.7692, 32.3242) radius 5.08 clockwise from (33.6166, 37.0564) to (36.4994, 34.1766)
  arc A6 centre (21.3665, 36.3855) radius 5.08 clockwise from (21.3665, 41.4655) to (23.2139, 41.1177)
  arc A7 centre (-36.3855, -20.5361) radius 5.08 clockwise from (-41.1157, -22.3885) to (-41.4655, -20.5361)
  arc A8 centre (-31.7692, -32.3242) radius 5.08 clockwise from (-33.6166, -37.0564) to (-36.4994, -34.1766)
  arc A9 centre (-21.3665, -36.3855) radius 5.08 clockwise from (-21.3665, -41.4655) to (-23.2139, -41.1177)
  arc A10 centre (36.3855, -20.5361) radius 5.08 clockwise from (41.4655, -20.5361) to (41.1157, -22.3885)
  arc A11 centre (31.7692, -32.3242) radius 5.08 clockwise from (36.4994, -34.1766) to (33.6166, -37.0564)
  arc A12 centre (21.3665, -36.3855) radius 5.08 clockwise from (23.2139, -41.1177) to (21.3665, -41.4655)
  circle C6 centre (0, 0) radius 35.5256
  arc A13 centre (-24.1331, 36.3855) radius 5.08 clockwise from (-26.5185, 40.8706) to (-24.1331, 41.4655)
  arc A14 centre (24.1231, 36.3855) radius 5.08 clockwise from (24.1231, 41.4655) to (26.5251, 40.8618)
  point P1 (0, 0)
  point P2 (0, 0)
  point P13 (0, 0)
  point P3 (-41.4655, 0)
  point P23 (41.4655, 0)
  point P4 (0, 41.4655)
  point P33 (0, 41.4655)
  point P14 (-36.4994, 34.1766)
  point P27 (36.4994, 34.1766)
  point P15 (-33.6166, 37.0564)
  point P29 (33.6166, 37.0564)
  point P17 (-23.2139, 41.1177)
  point P30 (23.2139, 41.1177)
  point P18 (-21.3665, 41.4655)
  point P32 (21.3665, 41.4655)
  point P20 (-41.4655, 20.5361)
  point P24 (41.4655, 20.5361)
  point P21 (-41.1157, 22.3885)
  point P26 (41.1157, 22.3885)
  point P34 (-41.4655, 0)
  point P44 (0, -41.4655)
  point P38 (-36.4994, -34.1766)
  point P40 (-33.6166, -37.0564)
  point P41 (-23.2139, -41.1177)
  point P43 (-21.3665, -41.4655)
  point P35 (-41.4655, -20.5361)
  point P37 (-41.1157, -22.3885)
  point P45 (41.4655, 0)
  point P46 (41.4655, -20.5361)
  point P48 (41.1157, -22.3885)
  point P49 (36.4994, -34.1766)
  point P51 (33.6166, -37.0564)
  point P53 (23.2139, -41.1177)
  point P54 (21.3665, -41.4655)
  point P55 (0, -41.4655)
  point P57 (0, 0)
  point P58 (-1.0967, 0)
  point P56 (0, 0)
  point P59 (0, 0)
  point P6 (0, 0)
  point P63 (0, 41.4655)
  point P64 (-34.1546, 36.8093)
  point P61 (-25.4, 41.4655)
  point P62 (25.4, 41.4655)
  coincident P1 P2
  vertical L1
  horizontal L4
  equal C3 C4
  equal C3 C5
  equal C2 C5
  coincident P1 P13
  perpendicular L1 L7
  tangent L2 A1
  tangent L3 A1
  tangent L3 A2
  tangent L4 A2
  equal A1 A2
  tangent L1 A3
  tangent L2 A3
  equal A1 A3
  symmetric P3 L6 P23
  symmetric P4 L6 P33
  symmetric L6 P14 P27
  symmetric L6 P15 P29
  symmetric L6 A1 A5
  symmetric L6 P17 P30
  symmetric L6 P18 P32
  symmetric L6 A2 A6
  symmetric L6 P20 P24
  symmetric L6 P21 P26
  symmetric L6 A3 A4
  symmetric P3 L7 P34
  symmetric P4 L7 P44
  symmetric L7 P14 P38
  symmetric L7 P15 P40
  symmetric L7 A1 A8
  symmetric L7 P17 P41
  symmetric L7 P18 P43
  symmetric L7 A2 A9
  symmetric L7 P20 P35
  symmetric L7 P21 P37
  symmetric L7 A3 A7
  symmetric L7 P23 P45
  symmetric L7 P24 P46
  symmetric L7 P26 P48
  symmetric L7 A4 A10
  symmetric L7 P27 P49
  symmetric L7 P29 P51
  symmetric L7 A5 A11
  symmetric L7 P30 P53
  symmetric L7 P32 P54
  symmetric L7 A6 A12
  symmetric L7 P33 P55
  coincident P23 P45
  coincident P1 P57
  coincident L7 P58
  perpendicular L6 L20
  coincident P56 P59
  coincident P6 P56
  perpendicular L6 L22
  coincident P33 P63
  coincident A1 P64
  tangent A1 L24
  coincident L22 P63
  coincident P61 L24
  coincident P61 L22
  tangent L24 A13
  tangent L22 A13
  coincident P62 L23
  coincident P62 L22
  tangent L23 A14
  tangent L22 A14
  equal A13 A14
  dimension "d1" diameter C1 = 79.375 (= "3 1/8")
  dimension "d2" radius A1 = 5.08 (= "0.20")
  dimension "d10" = 82.931 (= "3.265")
  dimension "d11" = 82.931 (= "d10")
  dimension "d13" angle L6 L21 = 45 (= "Angular Dimension-2")
  dimension "d58" distance P61 P62 = 50.8 (= "2")
  dimension "d59" radius A13 = 5.08
extrude "Extrude1" new body sketch "Instrument Sketch" profile of C1 L1 L2 L3 L4 C2 C3 C4 C5 A1 A2 A3 L8 A4 L9 A5 L10 A6 L11 L12 A7 L13 A8 L14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 along normal blind 10.25
extrude "Extrude2" sketch "Instrument Sketch" profile of C1 C6 blind 3
chamfer "Chamfer1" distance 3
canvas "Canvas2"
canvas "Canvas3"
move "Move1"
fillet "Fillet1" radius 0.5 0.5969 (= "0.047   * 0.5")
fillet "Fillet2" radius 1
sketch "Sketch2" plane through (0, 2, 0) normal (0, 1, 0) x axis (-1, 0, 0)
  line L1 (-36.4994, -34.1766) -> (-41.1157, -22.3885)
  line L2 (-23.2139, -41.1177) -> (-33.6166, -37.0564)
  line L3 (21.3665, -41.4655) -> (-21.3665, -41.4655)
  line L4 (33.6166, -37.0564) -> (23.2139, -41.1177)
  line L5 (41.1157, -22.3885) -> (36.4994, -34.1766)
  line L6 (41.4655, 20.5361) -> (41.4655, -20.5361)
  line L7 (36.4994, 34.1766) -> (41.1157, 22.3885)
  line L8 (-24.1231, 41.4655) -> (24.1331, 41.4655)
  line L9 (-41.1157, 22.3885) -> (-36.4994, 34.1766)
  line L10 (-41.4655, -20.5361) -> (-41.4655, 20.5361)
  line L11 (0, 32.0284) -> (0, 40.649)
  line L12 (-1.5, -39.15) -> (1.5, -39.15)
  line L13 (-1.5, -41.65) -> (-1.5, -39.15)
  line L14 (1.5, -41.65) -> (-1.5, -41.65)
  line L15 (1.5, -39.15) -> (1.5, -41.65)
  line L16 (-1.5, -41.65) -> (1.5, -39.15)
  line L17 (1.5, -41.65) -> (-1.5, -39.15)
  line L18 (26.5185, 40.8706) -> (34.1546, 36.8093)
  line L19 (-33.6166, 37.0564) -> (-26.5251, 40.8618)
  circle C1 centre (-31.4309, -31.4309) radius 2.159
  circle C2 centre (31.4309, 31.4309) radius 2.159
  circle C3 centre (31.4309, -31.4309) radius 2.159
  circle C4 centre (-31.4309, 31.4309) radius 2.159
  circle C5 centre (0, 0) radius 35.5256
  arc A1 centre (-36.3855, -20.5361) radius 5.08 clockwise from (-41.1157, -22.3885) to (-41.4655, -20.5361)
  arc A2 centre (-31.7692, -32.3242) radius 5.08 clockwise from (-33.6166, -37.0564) to (-36.4994, -34.1766)
  arc A3 centre (-21.3665, -36.3855) radius 5.08 clockwise from (-21.3665, -41.4655) to (-23.2139, -41.1177)
  arc A4 centre (21.3665, -36.3855) radius 5.08 clockwise from (23.2139, -41.1177) to (21.3665, -41.4655)
  arc A5 centre (31.7692, -32.3242) radius 5.08 clockwise from (36.4994, -34.1766) to (33.6166, -37.0564)
  arc A6 centre (36.3855, -20.5361) radius 5.08 clockwise from (41.4655, -20.5361) to (41.1157, -22.3885)
  arc A7 centre (36.3855, 20.5361) radius 5.08 clockwise from (41.1157, 22.3885) to (41.4655, 20.5361)
  arc A8 centre (31.7692, 32.3242) radius 5.08 clockwise from (34.1546, 36.8093) to (36.4994, 34.1766)
  arc A9 centre (-31.7692, 32.3242) radius 5.08 clockwise from (-36.4994, 34.1766) to (-33.6166, 37.0564)
  arc A10 centre (-36.3855, 20.5361) radius 5.08 clockwise from (-41.4655, 20.5361) to (-41.1157, 22.3885)
  circle C6 centre (0, 0) radius 39.65
  arc A11 centre (24.1331, 36.3855) radius 5.08 clockwise from (24.1331, 41.4655) to (26.5185, 40.8706)
  arc A12 centre (-24.1231, 36.3855) radius 5.08 clockwise from (-26.5251, 40.8618) to (-24.1231, 41.4655)
  point P1 (0, 0)
  point P39 (0, 0)
  point P41 (0, 32.0284)
  point P42 (0, 35.3825)
  point P43 (0.742, 39.6431)
  point P48 (0, -40.4)
  point P46 (-1.5, -41.65)
  point P47 (1.5, -41.65)
  point P45 (-1.5, -39.15)
  coincident P1 P39
  vertical L11
  vertical P39 P41
  coincident L11 P42
  coincident C6 P43
  horizontal L12
  perpendicular L12 L13
  parallel L12 L14
  parallel L13 L15
  coincident L16 P48
  coincident L17 P48
  vertical P1 P48
  dimension "d19" diameter C6 = 79.3
  dimension "d50" distance P46 P47 = 3
  dimension "d51" distance P45 P46 = 2.5
  dimension "d67" distance C6 L14 = 2
extrude "Extrude3" cut sketch "Sketch2" profile of C5 C6 L12 L13 L14 L15 to an object offset -6.5
sketch "Sketch1" plane through (0, -4.75, 0) normal (0, 1, 0) x axis (-1, 0, 0)
  line L1 (0, 40.6) -> (0.6381, 39.4948)
  line L2 (-0.6381, 39.4948) -> (0, 40.6)
  line L3 (1.5, -39.6216) -> (1.5, -41.4655)
  line L4 (-1.5, -41.4655) -> (-1.5, -39.6216)
  line L5 (1.5, -41.4655) -> (-1.5, -41.4655)
  circle C1 centre (0, 0) radius 35.5256
  circle C2 centre (0, 0) radius 39.55
  arc A1 centre (0, 0) radius 39.65 clockwise from (-1.5, -39.6216) to (1.5, -39.6216)
  arc A2 centre (0, 0) radius 39.5 clockwise from (0.6381, 39.4948) to (-0.6381, 39.4948)
  point P1 (0, 0)
  point P3 (0, 0)
  coincident P1 P3
  concentric A1 A2
extrude "Extrude1" new body sketch "Sketch1" profile of C1 C2 A1 L1 L2 A2 L3 L4 along normal blind 3
sketch "Sketch1" plane through (0, -1.75, 0) normal (0, 1, 0) x axis (-1, 0, 0)
  line L1 (-1.5, -39.6216) -> (-1.5, -41.4655)
  line L2 (1.5, -41.4655) -> (1.5, -39.6216)
  line L3 (1.5, -41.15) -> (-1.5, -41.15)
  line L4 (1.35, -38.7521) -> (1.35, -39.6216)
  line L5 (-1.35, -38.2133) -> (-1.35, -39.6216)
  line L6 (-1.35, -41.3) -> (-1.35, -41.4655)
  line L7 (-1.35, -39.6216) -> (-1.35, -41.3)
  line L8 (-1.35, -41.3) -> (-1.5, -41.3)
  line L9 (1.35, -41.3) -> (-1.35, -41.3)
  line L10 (1.5, -41.3) -> (1.35, -41.3)
  line L11 (1.35, -41.4655) -> (1.35, -41.3)
  line L12 (1.35, -41.3) -> (1.35, -39.6216)
  circle C1 centre (0, 0) radius 39.65
  circle C2 centre (0, 0) radius 36.65
  circle C3 centre (0, 0) radius 39.5
  parallel L4 L12
  parallel L5 L7
  dimension "d25" diameter C1 = 79.3
  dimension "d29" = -3
  dimension "d68" = -0.15
  dimension "d69" = 0.15
extrude "Extrude1" new body sketch "Sketch1" profile of C1 C2 C3 L7 L10 L12 L4 L5 to an object bodies "Seal"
